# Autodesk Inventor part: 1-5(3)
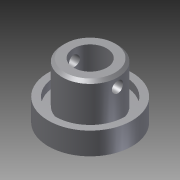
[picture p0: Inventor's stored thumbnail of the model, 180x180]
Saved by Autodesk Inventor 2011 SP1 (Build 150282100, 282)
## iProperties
Created: 2014-02
Part Number: 1-5(3)
Document SubType Name: Modeling
Designer: Administrator
Density: 1 g/cm^3
Author: Administrator
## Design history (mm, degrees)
sketch "草图1"
  geometry: C1 r 15 at (0, 0)
  constraints: 1 centre point
  dimensions: "d0" = 30 diameter of C1
extrude "拉伸1" new body sketch "草图1" distance "d1" = 8; taper "d2" = 0 deg
sketch "草图2"
  geometry: C1 r 15 at (0, 0) reference; C2 r 12.5 at (0, 0)
  constraints: 1 centre point, 1 coincident
  dimensions: "d3" = 25 diameter of C2
extrude "拉伸2" cut sketch "草图2" distance "d4" = 3; taper "d5" = 0 deg
sketch "草图3"
  geometry: C1 r 12.5 at (0, 0) reference; C2 r 10 at (0, 0)
  constraints: 1 centre point, 1 coincident
  dimensions: "d6" = 20 diameter of C2
extrude "拉伸3" join sketch "草图3" distance "d7" = 15; taper "d8" = 0 deg
chamfer "倒角1" distance "d9" = 1; stored, may be unused: second distance "d10" = 2, angle "d11" = 45 deg
sketch "草图4"
  geometry: C1 r 9 at (0, 0) reference; C2 r 6 at (0, 0)
  constraints: 1 centre point, 1 coincident
  dimensions: "d12" = 12 diameter of C2
extrude "拉伸4" cut sketch "草图4" stored distance "d13" = 15; taper "d14" = 0 deg
node "工作平面1"
sketch "草图5"
  geometry: L1 (-9, 20)-(9, 20) reference; C1 r 2 at (0, 16); 1 further point
  constraints: 1 centre point
  dimensions: "d17" = 4 diameter of C1
extrude "拉伸5" cut sketch "草图5" stored distance "d18" = 15; taper "d19" = 0 deg
node "实体1"
other parameters: "d15" = 12
